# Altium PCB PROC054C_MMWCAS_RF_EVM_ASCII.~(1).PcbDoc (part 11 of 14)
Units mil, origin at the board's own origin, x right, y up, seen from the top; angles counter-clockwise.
Board outline 6299.21 x 5370.07 mil, 8 copper layers (L1 TOP, L2 GND, L3 SIGNAL 1, L4 GND, L5 SIGNAL 2, L6 SIGNAL 3, L7 GND, L8 BOTTOM), stack 53.5 mil thick; 775 components, 552 nets, 2648 pads, 7845 vias.
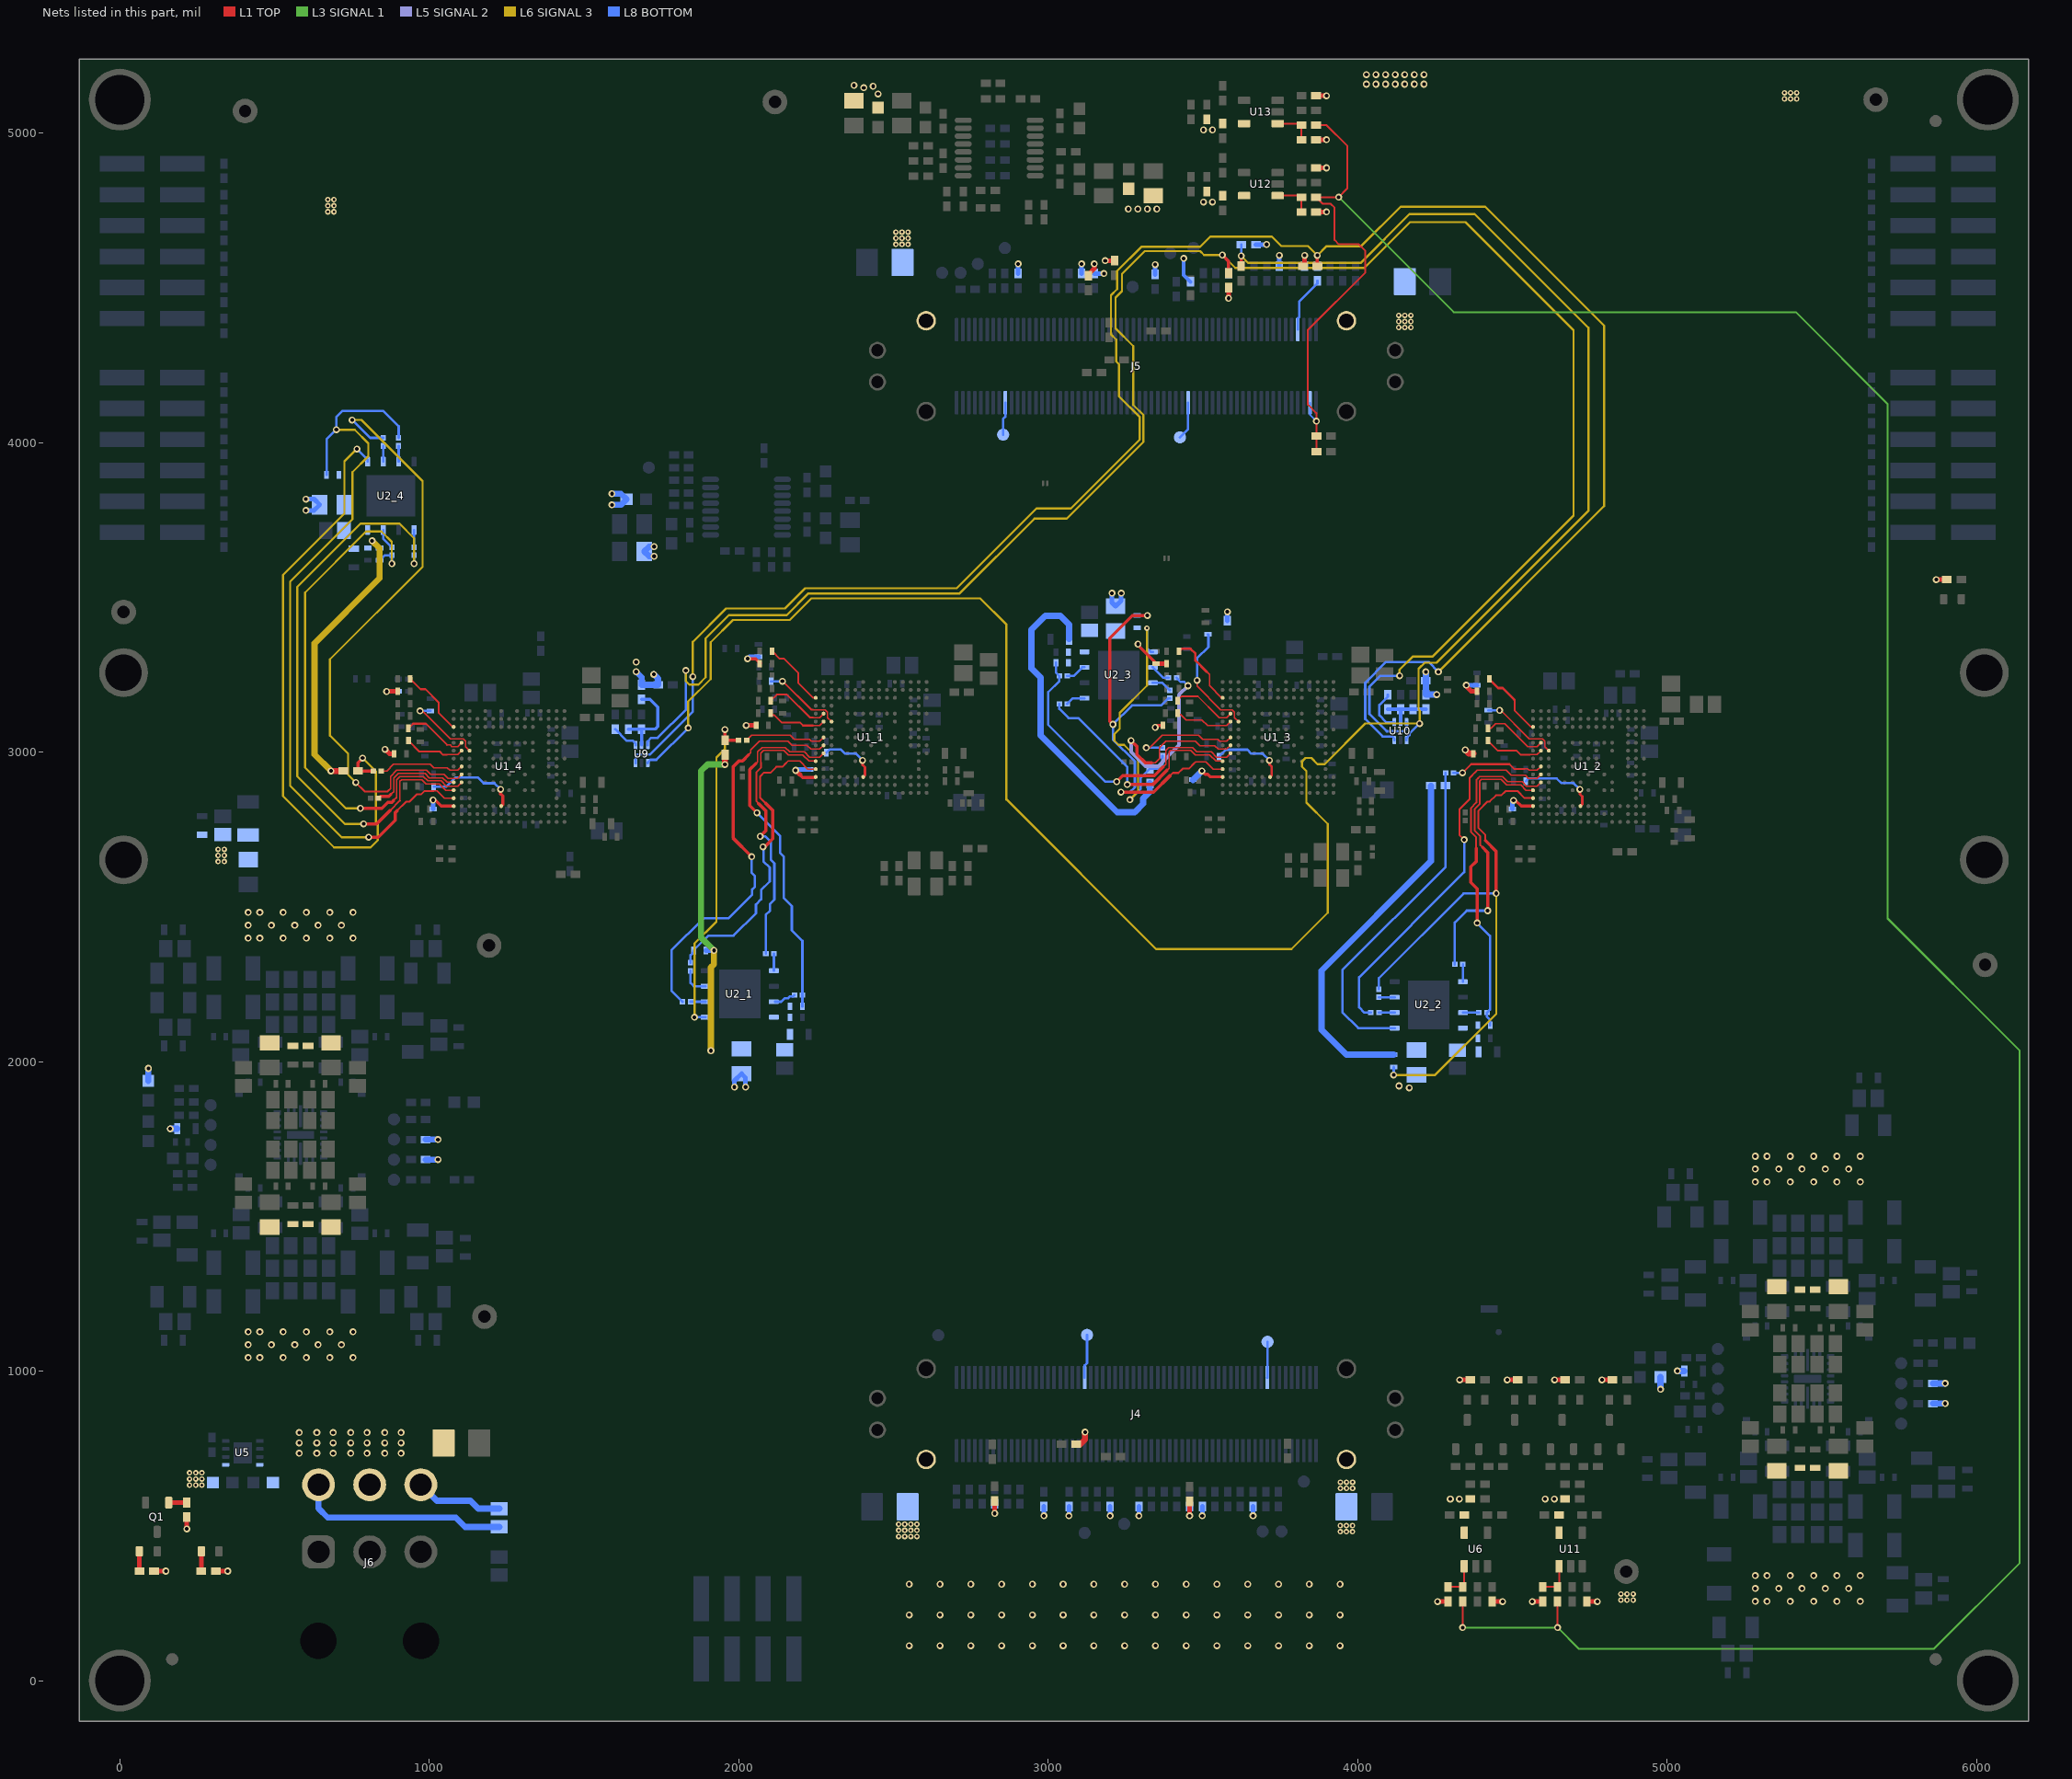
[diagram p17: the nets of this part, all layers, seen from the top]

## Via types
v1: diameter 13.77/15.74 (per signal layer), hole 5.9, L1 TOP to L2 GND, tented both sides, 5522 vias
v2: diameter 22.4, hole 12.2, L1 TOP to L8 BOTTOM, tented both sides, 1522 vias
v3: diameter 18, hole 8, L1 TOP to L8 BOTTOM, tented both sides, 727 vias
v4: diameter 18, hole 7.87, L1 TOP to L8 BOTTOM, tented top, 50 vias
v5: diameter 24, hole 12, L1 TOP to L8 BOTTOM, tented both sides, 13 vias
v6: diameter 19.68, hole 7.87, L1 TOP to L8 BOTTOM, tented top, 10 vias
v7: diameter 13.77/15.74 (per signal layer), hole 5.9, L1 TOP to L2 GND, tented top, 1 vias

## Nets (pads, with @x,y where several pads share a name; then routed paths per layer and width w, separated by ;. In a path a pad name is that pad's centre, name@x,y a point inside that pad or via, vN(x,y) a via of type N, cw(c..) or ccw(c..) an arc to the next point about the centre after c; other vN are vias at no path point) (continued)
QSPI_CLK_RS_4: R7_4.1 U1_4.R10 | length 312.9
  L1 TOP w4: 880,2867.56 885,2872.56 885,2916 900,2931 986,2931 1000,2917 1043,2917 1057.68,2902.32 U1_4.R10@1078.76,2902.31
  L1 TOP w6: 875.22,2862.78 880,2867.56
  L1 TOP w10.5: R7_4.1@836.23,2851.34 841.88,2857 869.44,2857 875.22,2862.78
QSPI_CS_1: R3_1.1 R6_1.2 U2_1.1 | length 1084.4
  L1 TOP w10.5: v2(1955.47,3072.76) R3_1.1@1955.47,3038.66 R6_1.2@1999.52,3038.66
  L6 SIGNAL 3 w6.9: v2(1856.94,2143.45) 1856.94,2381.49 1927.82,2452.37 1927.82,2982.73 1955.47,3010.37 v2(1955.47,3072.76)
  L8 BOTTOM w7.75: v2(1856.94,2143.45) U2_1.1@1893.07,2143.45
QSPI_CS_2: R3_2.1 R6_2.2 U2_2.1 | length 1101.7
  L8 BOTTOM w7.75: U2_2.1@4119.72,2108.17 4002.27,2108.17 3950.66,2159.79 3950.66,2295.48 4284.5,2629.32 R3_2.1@4284.5,2891.34 R6_2.2@4284.5,2932.79
QSPI_CS_3: R3_3.1 R6_3.2 U2_3.1 | length 942.7
  L6 SIGNAL 3 w6.9: v2(3263.95,2846.06) 3290.69,2872.8 3290.69,2978.19 3245.33,3023.55 3227.38,3023.55 3213.98,3036.95 3213.98,3058.37 3230.89,3075.29 3230.89,3126.62 3319.33,3215.06 v3(3319.33,3400.73)
  L8 BOTTOM w7.75: v2(3263.95,2846.06) 3299.18,2881.29 3299.18,2916.68 R3_3.1@3328.84,2946.33 3357.8,2946.33 3369.29,2957.81 R6_3.2@3369.29,2988.02 ; v3(3319.33,3400.73) 3319.33,3336.15 3331.48,3324 U2_3.1@3338.2,3324
QSPI_CS_4: R3_4.1 R6_4.2 U2_4.1 | length 2043.6
  L1 TOP w10.5: v2(784.43,2980.78) 769.58,2965.93 R3_4.1@769.58,2938.96 R6_4.2@818.79,2938.96
  L6 SIGNAL 3 w6.9: v2(765.87,3979.55) 725.55,3939.23 725.55,3770.66 527.16,3572.27 527.16,2857.64 692.53,2692.26 810.51,2692.26 833.15,2714.9 833.15,2765.55 827.8,2770.91 827.8,2937.42 v2(784.43,2980.78)
  L8 BOTTOM w7.75: v2(765.87,3979.55) 800.89,3944.53 U2_4.1@800.89,3938.33
QSPI_CS_RS_1: R6_1.1 U1_1.P8 | length 269.1
  L1 TOP w4: R6_1.1@2025.51,3038.66 2041.85,3055 2166.75,3055 2180,3041.75 2228.1,3041.75 2234.85,3035 2261.85,3035 U1_1.P8@2274.35,3047.5
QSPI_CS_RS_2: R6_2.1 U1_2.P8 | length 308
  L1 TOP w4: 4540.65,2946 4549,2946 4554,2941 4579.85,2941 U1_2.P8@4592.35,2953.5
  L1 TOP w6: v2(4339,2933) 4367,2961 4491,2961 4506,2946 4540.65,2946
  L8 BOTTOM w7.75: R6_2.1@4309.42,2933 v2(4339,2933)
QSPI_CS_RS_3: R6_3.1 U1_3.P8 | length 355.1
  L1 TOP w4: v2(3317,3014) 3327.98,3014 3368.98,3055 3486,3055 3500,3041 3548,3041 3554,3035 3576.85,3035 U1_3.P8@3589.35,3047.5
  L8 BOTTOM w7.75: v2(3317,3014) R6_3.1@3369.29,3014
QSPI_CS_RS_4: R6_4.1 U1_4.P8 | length 282.2
  L1 TOP w4: R6_4.1@844.78,2938.96 862.49,2938.96 884.54,2961 1003,2961 1015,2949 1058,2949 1066,2941 1091.85,2941 U1_4.P8@1104.35,2953.5
QSPI_D0_1: R30_1.1 U1_1.R11 | length 907.9
  L1 TOP w4: 2071.51,2965.93 2071.51,2996.51 2080,3005 2146,3005 2160,2991 2207,2991 2227.27,2970.73 U1_1.R11@2248.76,2970.72
  L1 TOP w6: 2064.5,2833.5 2056.46,2841.54 2056.46,2934.62 2071.51,2949.67 2071.51,2965.93
  L1 TOP w10.5: 2064.5,2833.5 2087.05,2810.95 2087.05,2745.55 v2@2069.4,2727.9
  L8 BOTTOM w7.75: v2@2069.4,2727.9 2084.8,2727.9 2104.25,2708.45 2104.25,2651.51 2115.19,2640.57 2115.19,2523.48 2100.57,2508.86 2100.57,2486.64 2087.55,2473.63 R30_1.1@2087.55,2349.27
  other v2: 2069.4,2727.78
QSPI_D0_2: R30_2.1 U1_2.R11 | length 888.5
  L1 TOP w4: 4394.22,2905.78 4400.02,2911.57 4463.43,2911.57 4481,2894 4527,2894 4544.27,2876.73 U1_2.R11@4566.76,2876.73
  L1 TOP w6: 4394.22,2905.78 4394.22,2832.02 4378,2815.79 4378,2747 4396.72,2728.28 4396.72,2699.28 4404,2692
  L1 TOP w10.5: 4404,2692 4420,2676 v2(4420,2487.75)
  L8 BOTTOM w7.75: R30_2.1@4314.21,2313.99 4314.21,2449.21 4352.75,2487.75 v2(4420,2487.75)
QSPI_D0_3: R30_3.1 U1_3.R11 | length 769.6
  L1 TOP w4: 3383.9,2940.91 3390.9,2947.91 3390.9,3000.9 3395,3005 3461,3005 3475,2991 3522,2991 3542.27,2970.73 U1_3.R11@3563.76,2970.72
  L1 TOP w10.5: v2(3255.64,2895.06) 3338.05,2895.06 3383.9,2940.91
  L8 BOTTOM w7.75: R30_3.1@3035.84,3156 3035.84,3139.82 3065.47,3110.18 3097.36,3110.18 3255.64,2951.9 v2(3255.64,2895.06)
QSPI_D0_4: R30_4.1 U1_4.R11 | length 1881.4
  L1 TOP w4: 905,2843.15 905,2906 910,2911 976,2911 990,2897 1033,2897 1053.27,2876.73 U1_4.R11@1078.76,2876.72
  L1 TOP w6: 873.33,2811.48 905,2843.15
  L1 TOP w10.5: v2(788,2768) 829.85,2768 873.33,2811.48
  L6 SIGNAL 3 w6.9: v2(788,2768) 726.98,2768 573.41,2921.58 573.41,3533.58 777.75,3737.93 903.6,3737.93 950.89,3690.64 v2(950.89,3609.06)
  L8 BOTTOM w7.75: v2(950.89,3609.06) R30_4.1@950.89,3635.98
QSPI_D0_RS_1: R30_1.2 U2_1.5 | length 55.8
  L8 BOTTOM w7.75: U2_1.5@2113.54,2293.45 R30_1.2@2113.54,2349.27
QSPI_D0_RS_2: R30_2.2 U2_2.5 | length 55.8
  L8 BOTTOM w7.75: U2_2.5@4340.2,2258.17 R30_2.2@4340.2,2313.99
QSPI_D0_RS_3: R30_3.2 U2_3.5 | length 63.4
  L8 BOTTOM w7.75: R30_3.2@3061.82,3156 3079.82,3174 U2_3.5@3117.72,3174
QSPI_D0_RS_4: R30_4.2 U2_4.5 | length 55.9
  L8 BOTTOM w7.75: R30_4.2@950.89,3661.96 U2_4.5@950.89,3717.86
QSPI_D1_1: R31_1.1 U1_1.P9 | length 1310.7
  L1 TOP w4: 2031.08,2990.33 2038.41,2997.67 2038.41,3007.02 2066.41,3035.01 2158.44,3035.01 2171.7,3021.75 2220.25,3021.75 2232.59,3009.41 2261.85,3009.41 U1_1.P9@2274.35,3021.91
  L1 TOP w10.5: 2031.08,2990.33 2012.46,2971.71 2000.63,2971.71 1981.44,2952.51 1981.44,2722.56 v2@2042,2662
  L8 BOTTOM w7.75: R31_1.1@1818.27,2193.45 1782.88,2228.84 1782.88,2360.24 1885.77,2463.13 1967.11,2463.13 2043.52,2539.54 2043.52,2556.03 2052.39,2564.9 2052.39,2599.49 2042,2609.89 v2@2042,2662
  other v2: 2042,2661.88
QSPI_D1_2: R31_2.1 U1_2.P9 | length 1203.9
  L1 TOP w4: 4380.69,2935.34 4386.35,2941 4480,2941 4496,2925 4542,2925 4551.59,2915.41 4579.85,2915.41 U1_2.P9@4592.35,2927.91
  L1 TOP w6: v2(4344.52,2716.87) 4328.62,2732.77 4328.62,2814.56 4362.05,2847.99 4362.05,2916.7 4380.69,2935.34
  L8 BOTTOM w7.75: R31_2.1@4042.84,2158.17 4021.86,2158.17 4004.78,2175.25 4004.78,2272.33 4344.52,2612.07 v2(4344.52,2716.87)
QSPI_D1_3: R31_3.1 U1_3.P9 | length 921.7
  L1 TOP w4: 3334.56,2965 3345.76,2965 3360,2979.24 3360,3014.15 3380.85,3035 3476,3035 3490,3021 3538,3021 3549.59,3009.41 3576.85,3009.41 U1_3.P9@3589.35,3021.91
  L1 TOP w10.5: v2(3268,3037) 3286.57,3018.43 3286.57,2992.7 3314.27,2965 3334.56,2965
  L5 SIGNAL 2 w12: v2(3268,3037) 3268,3000.23 3313.86,2954.37 3355.2,2954.37 3422.88,3022.05 3422.88,3185.44 v2(3451.8,3214.36)
  L8 BOTTOM w7.75: R31_3.1@3415.08,3239.82 3427.88,3227.02 3439.14,3227.02 v2(3451.8,3214.36)
QSPI_D1_4: R31_4.1 U1_4.P9 | length 1986
  L1 TOP w4: 869.32,2877.04 875,2882.72 875,2921 895,2941 991,2941 1004,2928 1048,2928 1060.59,2915.41 1091.85,2915.41 U1_4.P9@1104.35,2927.91
  L1 TOP w6: v2(762.51,2901.82) 791.72,2872.61 864.89,2872.61 869.32,2877.04
  L6 SIGNAL 3 w6.9: v2(750.85,4073.17) 780.78,4073.17 978.24,3875.71 978.24,3598.76 679.14,3299.66 679.14,3053.48 737.32,2995.31 737.32,2927 v2(762.51,2901.82)
  L8 BOTTOM w7.75: v2(750.85,4073.17) 808.81,4015.21 R31_4.1@850.89,4015.21
QSPI_D1_RS_1: R31_1.2 U2_1.2 | length 48.8
  L8 BOTTOM w7.75: R31_1.2@1844.26,2193.45 U2_1.2@1893.07,2193.45
QSPI_D1_RS_2: R31_2.2 U2_2.2 | length 50.9
  L8 BOTTOM w7.75: R31_2.2@4068.82,2158.17 U2_2.2@4119.72,2158.17
QSPI_D1_RS_3: R31_3.2 U2_3.2 | length 65.1
  L8 BOTTOM w7.75: U2_3.2@3338.2,3274 3372.38,3239.82 R31_3.2@3389.1,3239.82
QSPI_D1_RS_4: R31_4.2 U2_4.2 | length 50.9
  L8 BOTTOM w7.75: U2_4.2@850.89,3938.33 R31_4.2@850.89,3989.23
QSPI_D2_1: R27_1.2 R32_1.1 U1_1.R12 | length 1009.3
  L1 TOP w4: 2189.08,2971 2197,2971 2222.86,2945.14 U1_1.R12@2248.76,2945.13
  L1 TOP w4.9: 2153.81,2965.29 2159.52,2971 2189.08,2971
  L1 TOP w6: 2088,2834 2069,2853 2069,2921.42 2081.58,2934 2103.44,2934 2121.77,2952.32 2140.84,2952.32 2153.81,2965.29
  L1 TOP w10.5: v2@2078.5,2694.1 2084.43,2694.1 2110.35,2720.02 2110.35,2811.65 2088,2834
  L8 BOTTOM w7.75: R32_1.1@1844.26,2319.43 1844.26,2343.58 1854.26,2353.58 R27_1.2@1854.26,2359.18 1902.03,2406.95 1983.18,2406.95 2055.67,2479.44 2055.67,2507.44 2072.49,2524.26 2072.49,2554.39 2100.18,2582.09 2100.18,2626.82 2080,2647 2080,2692.6 v2@2078.5,2694.1
  other v2: 2078.5,2693.98
QSPI_D2_2: R27_2.2 R32_2.1 U1_2.R12 | length 1859.4
  L1 TOP w6: 4413.01,2713.99 4413.01,2731.99 4390.35,2754.65 4390.35,2810.73 4419.98,2840.35 4427.2,2840.35 4446.85,2860 4464.17,2860 4478.17,2874 4517,2874 4539.87,2851.13 U1_2.R12@4566.76,2851.13
  L1 TOP w10.5: 4413.01,2713.99 4448,2679 v2(4448,2543.39)
  L6 SIGNAL 3 w6.9: v2(4116.64,1956.94) 4250.75,1956.94 4448,2154.2 v2(4448,2543.39)
  L8 BOTTOM w7.75: R32_2.1@4068.82,2234.15 4068.82,2270 4342.21,2543.39 v2(4448,2543.39) ; v2(4116.64,1956.94) R27_2.2@4116.64,1982.51
QSPI_D2_3: R27_3.2 R32_3.1 U1_3.R12 | length 1344.2
  L1 TOP w4: 3471.82,2963.62 3477.2,2969 3510,2969 3533.86,2945.14 U1_3.R12@3563.76,2945.13
  L1 TOP w6: 3394.44,2924.44 3402.79,2932.79 3420.79,2932.79 3434.67,2946.67 3454.87,2946.67 3471.82,2963.62
  L1 TOP w10.5: v2(3209,3089.6) 3198.84,3099.75 3198.84,3368.15 3271.94,3441.24 v2(3320.35,3441.24) ; v2(3235.29,2870.65) 3340.65,2870.65 3394.44,2924.44
  L8 BOTTOM w7.75: v2(3235.29,2870.65) 3264.43,2870.65 3280.08,2886.3 3280.08,2969.98 3209,3041.06 v2(3209,3089.6) 3270.53,3151.13 3365.27,3151.13 3388.02,3173.88 R32_3.1@3393.01,3173.88 ; R27_3.2@3292.73,3441.24 v2(3320.35,3441.24)
QSPI_D2_4: R27_4.2 R32_4.1 U1_4.R12 | length 2483.7
  L1 TOP w4: 1014.53,2874.24 1025.76,2874.24 1048.86,2851.14 U1_4.R12@1078.76,2851.13
  L1 TOP w6: 896.36,2811.17 925,2839.81 935.7,2839.81 958.92,2863.04 973.3,2863.04 984.5,2874.24 1014.53,2874.24
  L1 TOP w10.5: v2(804,2725) 835.1,2725 889.39,2779.29 889.39,2804.2 896.36,2811.17
  L6 SIGNAL 3 w6.9: v2(699.62,4041.66) 758.97,4041.66 803.02,3997.61 803.02,3955.88 751.72,3904.58 751.72,3752.25 550.28,3550.81 550.28,2891.36 716.65,2725 v2(804,2725)
  L8 BOTTOM w7.75: R27_4.2@668.22,3895.75 668.22,4010.26 v2(699.62,4041.66) 699.62,4082.81 719.53,4102.72 850.89,4102.72 900.89,4052.72 R32_4.1@900.89,4015.21
QSPI_D2_RS_1: R32_1.2 U2_1.3 | length 92.4
  L8 BOTTOM w7.75: R32_1.2@1844.26,2293.44 1844.26,2254.36 1855.17,2243.45 U2_1.3@1893.07,2243.45
QSPI_D2_RS_2: R32_2.2 U2_2.3 | length 50.9
  L8 BOTTOM w7.75: R32_2.2@4068.82,2208.17 U2_2.3@4119.72,2208.17
QSPI_D2_RS_3: R32_3.2 U2_3.3 | length 64.8
  L8 BOTTOM w7.75: U2_3.3@3338.2,3224 3368.87,3224 R32_3.2@3393.01,3199.87
QSPI_D2_RS_4: R32_4.2 U2_4.3 | length 50.9
  L8 BOTTOM w7.75: U2_4.3@900.89,3938.33 R32_4.2@900.89,3989.23
QSPI_D3_1: R28_1.2 R33_1.1 U1_1.P10 | length 1141
  L1 TOP w4: 2054.98,2962.98 2060.79,2968.79 2060.79,3000.79 2075.01,3015.01 2150.14,3015.01 2164.15,3001 2212,3001 2229.18,2983.82 2261.85,2983.82 U1_1.P10@2274.35,2996.31
  L1 TOP w10.5: 2054.98,2962.98 2035.81,2943.81 2035.81,2827.19 v2@2059,2804
  L8 BOTTOM w7.75: v2@2059,2804 2134,2729 2134,2673.76 2145.86,2661.9 2145.86,2528.37 2171.6,2502.63 2171.6,2424.11 2205.91,2389.81 R33_1.1@2205.91,2215.45 R28_1.2@2205.91,2178.18
  other v2: 2059,2803.88
QSPI_D3_2: R28_2.2 R33_2.1 U1_2.P10 | length 1078.6
  L1 TOP w4: 4388.98,2915.33 4393.85,2920.2 4468.95,2920.2 4485.15,2904 4532,2904 4546.18,2889.82 4579.85,2889.82 U1_2.P10@4592.35,2902.32
  L1 TOP w6: 4383,2688.83 4383,2725 4366,2742 4366,2818.96 4384.12,2837.08 4384.12,2910.47 4388.98,2915.33
  L1 TOP w10.5: 4383,2688.83 4383,2646.71 4366,2629.71 4366,2578.75 4386.34,2558.41 v2(4386.34,2447.74)
  L8 BOTTOM w7.75: v2(4386.34,2447.74) 4428.03,2406.05 4428.03,2168.13 R33_2.1@4418.08,2158.17 4418.08,2145.12 4428.64,2134.56 R28_2.2@4428.64,2117.67
QSPI_D3_3: R28_3.2 R33_3.1 U1_3.P10 | length 974.8
  L1 TOP w4: 3370.96,2952.36 3380,2961.4 3380,3005 3390,3015 3466,3015 3480,3001 3527,3001 3544.18,2983.82 3576.85,2983.82 U1_3.P10@3589.35,2996.31
  L1 TOP w10.5: v2(3221.41,2904.61) 3240.98,2924.17 3342.78,2924.17 3370.96,2952.36
  L8 BOTTOM w7.75: R28_3.2@3025.36,3289.27 3025.36,3256.48 R33_3.1@3035.84,3246 3035.84,3229.7 3000.02,3193.88 3000.02,3088.53 3183.94,2904.61 v2(3221.41,2904.61)
QSPI_D3_4: R28_4.2 R33_4.1 U1_4.P10 | length 1739
  L1 TOP w4: 892.97,2851.96 895,2853.99 895,2910.99 905,2920.99 981,2920.99 995,2906.99 1038,2906.99 1055.18,2889.81 1091.85,2889.81 U1_4.P10@1104.35,2902.31
  L1 TOP w6: 884.5,2843.49 892.97,2851.96
  L1 TOP w10.5: v2(777.5,2818.49) 846.59,2818.49 866.09,2837.99 879,2837.99 884.5,2843.49
  L6 SIGNAL 3 w6.9: v2(777.5,2818.49) 730.21,2818.49 598.6,2950.1 598.6,3515.57 795.79,3712.77 845.26,3712.77 878.89,3679.14 v2(878.89,3609.06)
  L8 BOTTOM w7.75: R28_4.2@839.38,3619.4 855.95,3635.98 R33_4.1@878.89,3635.98 v2(878.89,3609.06)
QSPI_D3_RS_1: R33_1.2 U2_1.7 | length 71.6
  L8 BOTTOM w7.75: U2_1.7@2117.47,2193.45 2137.37,2193.45 2149.08,2205.16 2159.64,2205.16 2165.33,2210.86 2175.33,2210.86 R33_1.2@2179.92,2215.45
QSPI_D3_RS_2: R33_2.2 U2_2.7 | length 51.9
  L8 BOTTOM w7.75: U2_2.7@4340.2,2158.17 R33_2.2@4392.1,2158.17
QSPI_D3_RS_3: R33_3.2 U2_3.7 | length 67.5
  L8 BOTTOM w7.75: R33_3.2@3061.82,3246 3082.81,3246 3110.81,3274 U2_3.7@3117.72,3274
QSPI_D3_RS_4: R33_4.2 U2_4.7 | length 67.5
  L8 BOTTOM w7.75: U2_4.7@850.89,3717.86 850.89,3689.96 R33_4.2@878.89,3661.96
QSPI_FLASH_3V3_1: C6_1.1 C7_1.1 C8_1.1 R3_1.2 R27_1.1 R28_1.1 R29_1.1 U2_1.8 | length 1068.6
  L1 TOP w20: v2(1955.47,2960.16) R3_1.2@1955.47,2991.41
  L3 SIGNAL 1 w20: v2(1920.09,2359.18) 1877.94,2401.33 1877.94,2938.65 1899.46,2960.16 v2(1955.47,2960.16)
  L6 SIGNAL 3 w20: v2(1910.09,2035.18) 1910.09,2304.57 1920.09,2314.57 v2(1920.09,2359.18)
  L8 BOTTOM w15: R27_1.1@1894.26,2359.18 v2(1920.09,2359.18)
QSPI_FLASH_3V3_2: C6_2.1 C7_2.1 C8_2.1 R3_2.2 R27_2.1 R28_2.1 R29_2.1 U2_2.8 | length 1201.7
  L8 BOTTOM w20: R27_2.1@4116.64,2022.51 3963.83,2022.51 3883.22,2103.12 3883.22,2293.73 4237.25,2647.76 R3_2.2@4237.25,2891.34
QSPI_FLASH_3V3_3: C6_3.1 C7_3.1 C8_3.1 R3_3.2 R27_3.1 R28_3.1 R29_3.1 U2_3.8 | length 1073.9
  L8 BOTTOM w20: C7_3.1@3067.86,3364.87 3067.86,3412.18 3039.51,3440.52 2990.81,3440.52 2946.13,3395.84 2946.13,3270.34 2975.25,3241.22 2975.25,3053.67 3222.91,2806 3279.58,2806 3306.8,2833.22 3306.8,2850.13 3328.84,2872.17 R3_3.2@3328.84,2899.09
QSPI_FLASH_3V3_4: C6_4.1 C7_4.1 C8_4.1 R3_4.2 R27_4.1 R28_4.1 R29_4.1 U2_4.8 | length 903.2
  L1 TOP w20: v2(682.32,2938.96) R3_4.2@722.34,2938.96
  L6 SIGNAL 3 w20: v2(682.32,2938.96) 629.15,2992.12 629.15,3351.52 839.49,3561.86 839.49,3658.66 v2(815.19,3682.96)
SDA_RS_1: R13_1.2 U1_1.R3 | length 221.9
  L1 TOP w6: R13_1.2@2108,3326 2132.6,3301.4 2146.9,3301.4 2192,3256.29 2192,3224.18 2240.73,3175.45 U1_1.R3@2248.76,3175.45
SDA_RS_2: R13_2.2 U1_2.R3 | length 225.8
  L1 TOP w6: 4507,3168.16 4507,3134.97 4560.52,3081.45 U1_2.R3@4566.76,3081.45
  L1 TOP w8: R13_2.2@4425.9,3237 4425.9,3235.1 4454.14,3206.86 4468.3,3206.86 4507,3168.16
SDA_RS_3: R13_3.2 U1_3.R3 | length 244.1
  L1 TOP w4: 3512.28,3259.72 3521,3251 3521,3214.56 3560.11,3175.45 U1_3.R3@3563.76,3175.45
  L1 TOP w8: R13_3.2@3422.9,3326 3430.8,3333.9 3460.21,3333.9 3475.94,3318.16 3475.94,3296.06 3512.28,3259.72
SDA_RS_4: R13_4.2 U1_4.R3 | length 225.1
  L1 TOP w4: 1053.68,3103.12 1075.35,3081.45 U1_4.R3@1078.76,3081.45
  L1 TOP w6: R13_4.2@937.9,3237 971.67,3203.23 987.47,3203.23 1029.87,3160.83 1029.87,3126.93 1053.68,3103.12
SPI_HOST_INTR1_RS_1: R10_1.1 U1_1.P6 | length 193.3
  L1 TOP w4: 2240.01,3085.86 2261.53,3085.86 U1_1.P6@2274.35,3098.68
  L1 TOP w6: R10_1.1@2103,3126 2109.12,3119.88 2114.54,3119.88 2138.62,3095.8 2197.43,3095.8 2207.37,3085.86 2240.01,3085.86
SPI_HOST_INTR1_RS_2: R10_2.1 U1_2.P6 | length 195.4
  L1 TOP w4: 4556.13,2991.86 4579.53,2991.86 U1_2.P6@4592.35,3004.68
  L1 TOP w6: R10_2.1@4420.91,3037 4452.45,3005.46 4513.1,3005.46 4526.7,2991.86 4556.13,2991.86
SPI_HOST_INTR1_RS_3: R10_3.1 U1_3.P6 | length 192.1
  L1 TOP w4: R10_3.1@3418.91,3126 3423.89,3121.02 3428.5,3121.02 3445.15,3104.37 3496.94,3104.37 3515.13,3086.18 3576.85,3086.18 U1_3.P6@3589.35,3098.68
SPI_HOST_INTR1_RS_4: R10_4.1 U1_4.P6 | length 195.5
  L1 TOP w4: 1056.91,2992.18 1091.85,2992.18 U1_4.P6@1104.35,3004.68
  L1 TOP w6: R10_4.1@933,3037 933,3036.28 967.48,3001.79 1033.74,3001.79 1043.36,2992.18 1056.91,2992.18
SPI_MISO1_RS_1: R12_1.1 U1_1.P5 | length 215.6
  L1 TOP w4: 2239.63,3111.77 2261.85,3111.77 U1_1.P5@2274.35,3124.27
  L1 TOP w6: R12_1.1@2103,3166 2123,3186 2155.62,3186 2229.85,3111.77 2239.63,3111.77
SPI_MISO1_RS_2: R12_2.1 U1_2.P5 | length 213.6
  L1 TOP w4: 4557.73,3017.77 4579.85,3017.77 U1_2.P5@4592.35,3030.27
  L1 TOP w4.9: R12_2.1@4420.89,3077 4431.03,3077 4446.03,3092 4476,3092 4550.23,3017.77 4557.73,3017.77
SPI_MISO1_RS_3: R12_3.1 U1_3.P5 | length 211
  L1 TOP w4: 3548.24,3115.92 3552.39,3111.77 3576.85,3111.77 U1_3.P5@3589.35,3124.27
  L1 TOP w4.9: R12_3.1@3418.89,3166 3418.89,3167.92 3431.24,3180.27 3483.89,3180.27 3548.24,3115.92
SPI_MISO1_RS_4: R12_4.1 U1_4.P5 | length 213.4
  L1 TOP w4: 1057.76,3023.24 1067.76,3023.24 1073.23,3017.77 1091.85,3017.77 U1_4.P5@1104.35,3030.27
  L1 TOP w6: R12_4.1@932.89,3077 947.68,3091.79 989.21,3091.79 1057.76,3023.24
SYSTEM_1V8: C18.1 C19.1 C20.1 C175.1 L34.1 R35.2
  other v2: 3259.09,4754.58 3289.73,4754.58 3320.38,4754.58 3351.02,4754.58
  other v3: 317.57,2646.28 337.26,2646.28 317.57,2665.96 337.26,2665.96 317.57,2685.65 337.26,2685.65 672.2,4745.71 691.88,4745.71 672.2,4765.4 691.88,4765.4 672.2,4785.08 691.88,4785.08
SYSTEM_3V3: C148_1.1 C148_2.1 C148_3.1 C148_4.1 C162.1 C163.1 C164.1 C165.1 C169.1 C181.1 C197.1 C198.1 C203.1 L33.1 L35.1 R29_1.2 R29_2.2 R29_3.2 R29_4.2 R37.2 R46.1 R47.2 R61.2 R70.1 R71.2 R86.2 R87.2 R88.2 R89.2 R90.2 R91.2 R92.2 R93.2 R150.2 R164.1 R166.2 R167.2 R168.2 R173.1 R174_1.2 R174_2.2 R174_3.2 R174_4.2 R175_1.2 R175_2.2 R175_3.2 R175_4.2 R176_1.2 R176_2.2 R176_3.2 R176_4.2 R177_1.2 R177_2.2 R177_3.2 R177_4.2 R178_1.2 R178_2.2 R178_3.2 R178_4.2 R179_1.2 R179_2.2 R179_3.2 R179_4.2 R180_1.2 R180_2.2 R180_3.2 R180_4.2 R181_1.2 R181_2.2 R181_3.2 R181_4.2 R193.2 R195.2 R206.2 R207.2 U1_1.R13 U1_2.R13 U1_3.R13 U1_4.R13 U5.1 U6.5 U11.5 U12.5 U13.5 | length 3056.5
  L1 TOP w10: v2(1012,2845) 1019,2845 1038.45,2825.55 U1_4.R13@1078.76,2825.55 ; v2(2028.5,3301.5) 2054.7,3301.5 R180_1.2@2070.2,3286 ; 2198,2927 2207,2918 2247.21,2918 U1_1.R13@2248.76,2919.55 ; v2(3290,3349) 3290,3345.61 3349.08,3286.53 R181_3.2@3349.08,3286 ; v2(3346,3080) 3352,3086 R177_3.2@3373.6,3086 ; v2(3497,2939) 3507.39,2928.61 3515.55,2928.61 3524.16,2920 3563.31,2920 U1_3.R13@3563.76,2919.55 ; v2(4504,2844) 4510,2844 4528.45,2825.55 U1_2.R13@4566.76,2825.55
  L1 TOP w15: v2(216.13,489.93) R195.2@216.13,527.89 ; v2(857,3009) 871,2995 R177_4.2@886.4,2995 ; v2@862,3197 R180_4.2@897.91,3197 ; v2(2024,3086) R177_1.2@2056.4,3086 ; v2(2184,2941) 2198,2927 ; v2(2827.21,540.28) R176_1.2@2827.21,580.9 ; R175_4.2@3130.51,4539.69 3130.51,4543.91 3149,4562.41 v2(3149,4577.44) ; v2(3184.17,4587.61) R176_4.2@3215.4,4587.61 ; R181_3.2@3349.08,3286 R180_3.2@3382.91,3286 ; v2(3457,532.56) R175_2.2@3457,579.22 ; v2(3583,4466.2) R168.2@3583,4500 ; R166.2@3822.75,4570.25 3829,4576.49 v2(3829,4604.76) ; R91.2@3865.5,4745.42 v2(3899.65,4745.42) ; R90.2@3865.5,4887.63 v2(3899.65,4887.63) ; R93.2@3865.5,4978.47 v2(3899.65,4978.47) ; R92.2@3865.5,5120.67 v2(3899.65,5120.67) ; v2(4258.03,255.59) R87.2@4292.19,255.59 ; v2(4351.29,3216.41) 4351.29,3212 4366.29,3197 R180_2.2@4385.91,3197 ; R86.2@4434.39,255.59 v2(4468.55,255.59) ; v2(4564.48,255.59) R89.2@4598.64,255.59 ; R88.2@4740.84,255.59 v2(4775,255.59) ; v2(5869.75,3557.54) R193.2@5903.9,3557.54
  L1 TOP w20: R178_1.2@3090.34,764 3103.52,764 3119.1,779.58 v2(3119.1,802.9) ; v2(4348,3007) 4360,2995 R177_2.2@4374.4,2995
  L8 BOTTOM w10: v2(862,3195.9) R181_4.2@899.06,3195.9
  L8 BOTTOM w12: v2(3437.73,4595.35) 3437.73,4541.94 R178_3.2@3460,4519.67
  L8 BOTTOM w15: v2(601.18,3781.05) 627.69,3781.05 R29_4.2@645.87,3799.23 627.69,3817.41 v2(601.18,3817.41) ; C148_4.1@1012,2815.58 v2(1012,2845) ; v2(1985.88,1917.9) 1985.88,1937.82 R29_1.2@2009.01,1960.95 2022.13,1947.82 v2(2022.13,1917.9) ; v2(2028.5,3301.5) 2035.23,3308.23 R181_1.2@2063.84,3308.23 ; v2(2184,2941) 2187.28,2944.28 C148_1.1@2229,2944.28 ; v2(2827.21,540.28) R175_1.2@2827.21,570.9 ; R174_4.2@2903,4546.21 v2(2903,4577.44) ; v2(2986,532.56) R150.2@2986,563.18 ; v2(3067,532.56) R179_1.2@3067,563.18 ; R178_4.2@3108,4546.21 v2(3108,4577.44) ; R179_4.2@3149,4546.21 v2(3180.23,4546.21) ; v2(3200,532.56) R174_1.2@3200,563.18 ; v2(3206.11,3513.53) 3206.11,3483.19 R29_3.2@3218.01,3471.29 3236.19,3489.47 v2(3236.19,3513.53) ; v2(3293,532.56) R176_2.2@3293,563.18 ; R174_3.2@3346,4543.24 v2(3346,4575.08) ; v2(3457,532.56) R179_2.2@3457,563.18 ; v2(3498,532.56) R178_2.2@3498,563.18 ; R179_3.2@3578.91,3424.58 v2(3578.91,3453.53) ; v2(3662,532.56) R174_2.2@3662,563.18 ; R167.2@3671.24,4640.08 v2(3705.76,4640.08) ; R175_3.2@3747,4570.25 v2(3747,4604.76) ; R176_3.2@3829,4570.25 v2(3829,4604.76) ; v2(4351.29,3216.41) R181_2.2@4386.19,3216.41 ; C148_2.1@4500,2815.58 4500,2840 v2(4504,2844)
  L8 BOTTOM w20: R46.1@988.28,1683.21 v2(1028.15,1683.21) ; R47.2@988.28,1748.23 v2(1028.15,1748.23) ; v2(1590.21,3798.87) 1619.54,3798.87 L35.1@1637.54,3816.87 1619.54,3834.87 v2(1590.21,3834.87) ; v2(1668.58,3259.7) 1686.31,3241.98 R164.1@1686.31,3217.45 C197.1@1739.32,3217.44 1739.32,3237.56 v2(1725.47,3251.41) ; v2(1726.42,3632.62) 1710.6,3632.62 C181.1@1695.02,3648.2 1710.6,3663.78 v2(1726.42,3663.78) ; C148_3.1@3467.98,2909.98 v2(3497,2939) ; v2(4220.47,3259.25) C198.1@4220.47,3230.71 R173.1@4220.47,3185.83 v2(4255.81,3185.83) ; R70.1@5859,895.36 v2(5898.87,895.36) ; R71.2@5859,960.38 v2(5898.87,960.38)
  other v2: 4299.6,586.56 4329.13,586.56 4606.05,586.56 4635.58,586.56 4166.81,1915.43 4133.82,1921.54 1668.45,3290.77 3501.68,4777.32 3531.22,4777.32 3501.68,5010.37 3531.22,5010.37 2450.31,5126.39 2404.21,5146.62 2434.12,5151.52 2372.39,5154.46
  other v3: 4851.06,260.16 4870.74,260.16 4890.43,260.16 4851.06,279.85 4870.74,279.85 4890.43,279.85 225.44,631.86 245.12,631.86 264.81,631.86 225.44,651.54 245.12,651.54 264.81,651.54 225.44,671.23 245.12,671.23 264.81,671.23 5379.55,5110.56 5399.23,5110.56 5418.92,5110.56 5379.55,5130.25 5399.23,5130.25 5418.92,5130.25
SYSTEM_3V3_LED: Q1.1 R195.1 | length 58.3
  L1 TOP w15: Q1.1@157.85,575.13 R195.1@216.13,575.13
SYSTEM_3V3_LED_PW: DS3.1 R194.1 | length 63.8
  L1 TOP w15: R194.1@63.36,353.83 DS3.1@63.36,417.61
SYSTEM_5V0: C39.1 C44.1 C51.1 C56.1 C97.1 C102.1 C109.1 C114.1 C190.1 C191.1 C192.1 C193.1 C194.1 C202.1 J4.P3 J4.P4 J5.P1 J5.P2 J6.5 J6.6 L9.1 L10.1 L11.1 L12.1 L25.1 L26.1 L27.1 L28.1 R19.1 R34.2 R44.1 R59.2 R68.1 R192.2 R194.2 R196.2 R197.2 R200.2 R201.2 U5.8 | length 623.1
  L1 TOP w15: R194.2@110.6,353.83 v2(148.56,353.83) ; R192.2@310.6,353.83 v2(348.56,353.83) ; v2(4330.07,971.8) R196.2@4364.23,971.8 ; v2(4483.3,971.8) R201.2@4517.45,971.8 ; v2(4636.52,971.8) R197.2@4670.68,971.8 ; v2(4789.75,971.8) R200.2@4823.9,971.8
  L8 BOTTOM w20: R34.2@92.28,1938.09 v2(92.28,1977.96) ; v2(162.55,1783.21) R44.1@185.28,1783.21 ; J6.6@972.72,632.78 1024.38,581.12 1132.73,581.12 1158.2,555.65 R19.1@1226.16,555.65 ; v2(4978.78,941.32) R59.2@4978.78,981.19 ; v2(5033.27,1000.35) R68.1@5056.01,1000.35
  other v2: 2551.09,112.68 2650.53,112.68 2749.97,112.68 2849.41,112.68 2948.85,112.68 3048.29,112.68 3147.73,112.68 3247.17,112.68 3346.61,112.68 3446.05,112.68 3545.49,112.68 3644.94,112.68 3744.38,112.68 3843.82,112.68 3943.26,112.68 2551.09,212.12 2650.53,212.12 2749.97,212.12 2849.41,212.12 2948.85,212.12 3048.29,212.12 3147.73,212.12 3247.17,212.12 3346.61,212.12 3446.05,212.12 3545.49,212.12 3644.94,212.12 3744.38,212.12 3843.82,212.12 3943.26,212.12 5285.29,256.03 5322.96,256.03 5398.29,256.03 5473.63,256.03 5548.96,256.03 5624.29,256.03 5285.29,297.53 5360.63,297.53 5435.96,297.53 5511.29,297.53 5586.63,297.53 2551.09,311.56 2650.53,311.56 2749.97,311.56 2849.41,311.56 2948.85,311.56 3048.29,311.56 3147.73,311.56 3247.17,311.56 3346.61,311.56 3446.05,311.56 3545.49,311.56 3644.94,311.56 3744.38,311.56 3843.82,311.56 3943.26,311.56 5285.29,339.03 5322.96,339.03 5398.29,339.03 5473.63,339.03 5548.96,339.03 5624.29,339.03 579.51,734.71 636.51,734.71 689.21,734.71 746.21,734.71 798.91,734.71 855.91,734.71 908.61,734.71 579.51,768.04 636.51,768.04 689.21,768.04 746.21,768.04 798.91,768.04 855.91,768.04 908.61,768.04 579.51,801.37 636.51,801.37 689.21,801.37 746.21,801.37 798.91,801.37 855.91,801.37 908.61,801.37 414.57,1043.88 452.24,1043.88 527.57,1043.88 602.9,1043.88 678.24,1043.88 753.57,1043.88 414.57,1085.38 489.9,1085.38 565.24,1085.38 640.57,1085.38 715.9,1085.38 414.57,1126.88 452.24,1126.88 527.57,1126.88 602.9,1126.88 678.24,1126.88 753.57,1126.88 5285.29,1611.18 5322.96,1611.18 5398.29,1611.18 5473.63,1611.18 5548.96,1611.18 5624.29,1611.18 5285.29,1652.68 5360.63,1652.68 5435.96,1652.68 5511.29,1652.68 5586.63,1652.68 5285.29,1694.18 5322.96,1694.18 5398.29,1694.18 5473.63,1694.18 5548.96,1694.18 5624.29,1694.18 414.57,2399.04 452.24,2399.04 527.57,2399.04 602.9,2399.04 678.24,2399.04 753.57,2399.04 414.57,2440.54 489.9,2440.54 565.24,2440.54 640.57,2440.54 715.9,2440.54 414.57,2482.04 452.24,2482.04 527.57,2482.04 602.9,2482.04 678.24,2482.04 753.57,2482.04 4028.33,5158.13 4059.33,5158.13 4090.33,5158.13 4121.33,5158.13 4152.33,5158.13 4183.33,5158.13 4214.33,5158.13 4028.33,5189.13 4059.33,5189.13 4090.33,5189.13 4121.33,5189.13 4152.33,5189.13 4183.33,5189.13 4214.33,5189.13
  other v3: 2516.73,465.73 2536.41,465.73 2556.1,465.73 2575.78,465.73 3944.01,480.96 3963.69,480.96 3983.38,480.96 2516.73,485.42 2536.41,485.42 2556.1,485.42 2575.78,485.42 3944.01,500.65 3963.69,500.65 3983.38,500.65 2516.73,505.1 2536.41,505.1 2556.1,505.1 2575.78,505.1 3944.46,621.51 3964.14,621.51 3983.83,621.51 3944.46,641.2 3964.14,641.2 3983.83,641.2 4132.74,4371.76 4152.43,4371.76 4172.11,4371.76 4132.74,4391.45 4152.43,4391.45 4172.11,4391.45 4132.74,4411.13 4152.43,4411.13 4172.11,4411.13 2507.71,4640.63 2527.39,4640.63 2547.08,4640.63 2507.71,4660.32 2527.39,4660.32 2547.08,4660.32 2507.71,4680 2527.39,4680 2547.08,4680
SYSTEM_5V0_LED: DS1.1 R192.1 | length 63.8
  L1 TOP w15: R192.1@263.36,353.83 DS1.1@263.36,417.61
SYSTEM_5V0_SENSE: J6.4 R19.2 | length 685.3
  L8 BOTTOM w20: J6.4@642.01,632.78 642.01,556.46 671.54,526.93 1085.35,526.93 1115.69,496.59 R19.2@1226.16,496.59
SYSTEM_PGOOD: J5.119 R38.1 R62.1 R189.1 R204.1 R205.1 R212.1 | length 9560.7
  L1 TOP w6: R62.1@3865.5,5025.87 3899.65,5025.87 3966.41,4959.12 3966.41,4820.66 v2(3938.57,4792.82) R38.1@3865.5,4792.82 3886.67,4771.65 3912.34,4771.65 3925.32,4758.67 3925.32,4654.89 3939.38,4640.83 4003.94,4640.83 4024.92,4619.85 4024.92,4549.91 3839.48,4364.47 3839.48,4122.49 3867,4094.97 v2(3867,4069) R204.1@3867,4020.74 R205.1@3867,3971.03 ; v2(4339.59,171.43) R189.1@4339.59,255.59 ; v2(4646.04,171.43) R212.1@4646.04,255.59
  L3 SIGNAL 1 w6: v2(3938.57,4792.82) 4310.11,4421.29 5416.14,4421.29 5712.68,4124.75 5712.68,2462.43 6139.39,2035.73 6139.39,380.1 5861.89,102.6 4714.87,102.6 v2(4646.04,171.43) v2(4339.59,171.43)
  L8 BOTTOM w6: J5.119@3845.94,4128.84 3845.94,4090.06 v2(3867,4069)
SYSTEM_PGOOD1_GS: R87.1 R189.2 U6.1 | length 116.2
  L1 TOP w6: R87.1@4292.19,302.83 R189.2@4339.59,302.83 4344.59,307.83 U6.1@4344.59,369.58
SYSTEM_PGOOD2_GS: R89.1 R212.2 U11.1 | length 116.2
  L1 TOP w6: R89.1@4598.64,302.83 R212.2@4646.04,302.83 4651.04,307.83 U11.1@4651.04,369.58
SYSTEM_PGOOD3_GS: R38.2 R91.1 U12.1 | length 126.2
  L1 TOP w6: U12.1@3741.51,4797.82 3813.25,4797.82 R38.2@3818.25,4792.82 R91.1@3818.25,4745.42
SYSTEM_PGOOD4_GS: R62.2 R93.1 U13.1 | length 126.2
  L1 TOP w6: U13.1@3741.51,5030.87 3813.25,5030.87 R62.2@3818.25,5025.87 R93.1@3818.25,4978.47
TDO_RS_1: R8_1.1 U1_1.J13 | length 195.3
  L1 TOP w8: v2(2400.34,2973.54) 2400.34,2958.25 2407.9,2950.69 2407.9,2925.15 U1_1.J13@2402.3,2919.55
  L8 BOTTOM w7.75: R8_1.1@2283.7,2998.15 2294.54,3009 2329.72,3009 2343.1,2995.62 2378.26,2995.62 v2(2400.34,2973.54)
TDO_RS_2: R8_2.1 U1_2.J13 | length 252.2
  L1 TOP w8: v2(4718.34,2879.54) 4718.34,2864.33 4725.85,2856.82 4725.85,2831.1 U1_2.J13@4720.3,2825.55
  L8 BOTTOM w7.75: R8_2.1@4543.9,2906 4552.85,2914.95 4643.17,2914.95 4658.52,2899.6 4698.28,2899.6 v2(4718.34,2879.54)
TDO_RS_3: R8_3.1 U1_3.J13 | length 246.5
  L1 TOP w8: v2(3715.34,2973.54) 3715.34,2959.61 3722.42,2952.52 3722.42,2924.67 U1_3.J13@3717.3,2919.55
  L8 BOTTOM w7.75: R8_3.1@3551.46,2985.2 3574.07,3007.81 3643.97,3007.81 3656.78,2995 3693.88,2995 v2(3715.34,2973.54)
TDO_RS_4: R8_4.1 U1_4.J13 | length 303.5
  L1 TOP w10.5: v2(1230.34,2879.54) 1230.34,2865.07 1237.38,2858.03 1237.38,2830.63 U1_4.J13@1232.3,2825.55
  L8 BOTTOM w7.75: R8_4.1@1014.55,2887.78 1054.17,2887.78 1084.72,2918.33 1156.62,2918.33 1175.57,2899.38 1210.5,2899.38 v2(1230.34,2879.54)
TMP1_3V3: C195.1 C196.1 R164.2 U9.5 | length 275.9
  L8 BOTTOM w10: C196.1@1643.31,3074.22 C195.1@1686.31,3074.21 U9.5@1686.31,3022.83 ; C195.1@1685.85,3074.67 1730.43,3074.67 1738.85,3083.09 1738.85,3145.2 1713.84,3170.21 R164.2@1686.31,3170.21
TMP1_ADD0: R165.2 U9.4 | length 90.5
  L8 BOTTOM w7.75: R165.2@1600.31,3074.23 1637.33,3037.21 1657.15,3037.21 1666.62,3027.74 U9.4@1666.62,3022.83
TMP2_3V3: C199.1 C200.1 R172.2 R173.2 U10.5 | length 164.8
  L8 BOTTOM w12: R172.2@4097.47,3138.59 C199.1@4138.47,3138.59 ; U10.5@4138.47,3096.82 C199.1@4138.47,3138.59 ; R173.2@4220.47,3138.59 C200.1@4179.47,3138.59 C199.1@4138.47,3138.59
TMP2_ADD0: R172.1 U10.4 | length 136
  L8 BOTTOM w7.75: R172.1@4097.47,3185.83 4097.47,3179.4 4070.26,3152.19 4070.26,3118.68 4092.11,3096.82 U10.4@4118.78,3096.82
TMP_ALERT: R166.1 R171.1 U9.3 U10.3 | length 6598.6
  L1 TOP w10.5: R166.1@3870,4570.25 v2(3870,4604.76)
  L6 SIGNAL 3 w6.9: v2(1851.79,3243.79) 1851.79,3356.51 1959.25,3463.97 2149.42,3463.97 2215.05,3529.6 2704.08,3529.6 2961.93,3787.44 3073.61,3787.44 3296.09,4009.92 3296.09,4081.84 3228.63,4149.3 3228.63,4253.11 3219.81,4261.93 3219.81,4332.93 3202.98,4349.76 3202.98,4475.74 3223.09,4495.85 3223.09,4554.55 3300.9,4632.36 3490.56,4632.36 3523.75,4665.54 3722.99,4665.54 3753.7,4634.83 3839.93,4634.83 v2(3870,4604.76) 3899.9,4634.67 4011.69,4634.67 4139.57,4762.54 4411.8,4762.54 4796.75,4377.59 4796.75,3795.11 v2(4260.89,3259.25)
  L8 BOTTOM w7.75: U9.3@1666.62,2964.56 1666.62,2988.77 1669.85,2992 1712.42,2992 1851.79,3131.37 v2(1851.79,3243.79) ; R171.1@3870,4570.25 v2(3870,4604.76) ; U10.3@4118.78,3038.55 4118.78,3043.11 4111.62,3050.28 4081.14,3050.28 4024.49,3106.92 4024.49,3223.92 4091.57,3291 4229.14,3291 v2(4260.89,3259.25)
TMPSNS_ALERT: J5.57 R171.2 | length 184.2
  L8 BOTTOM w7.75: J5.57@3806.57,4365.06 3806.57,4401.09 3811.83,4406.34 3811.83,4456.14 3870,4514.31 R171.2@3870,4523
TMPSNS_SCL: R167.1 R170.1 U9.1 U10.1 | length 7378.8
  L1 TOP w10.5: R170.1@3624,4570.25 v2(3624,4603.07)
  L6 SIGNAL 3 w6.9: v2(1836.72,3078.07) 1836.72,3163.55 1909.35,3236.18 1909.35,3354.77 1981.58,3427 2165.17,3427 2235,3496.84 2780.31,3496.84 2865.28,3411.88 2865.28,2847.05 3348.79,2363.54 3785.84,2363.54 3903.46,2481.16 3903.46,2767.71 3834.43,2836.73 3834.43,2938.96 3819.98,2953.41 3819.98,2969.32 3831.77,2981.11 3850.7,2981.11 3871.14,2960.67 3893.33,2960.67 4025.02,3092.36 v2(4200.55,3092.36) 4200.55,3134.02 4197.18,3137.39 4197.18,3269.03 4216.87,3288.72 4255.16,3288.72 4745.78,3779.34 4745.78,4371.13 4378.51,4738.4 4167.47,4738.4 4009.39,4580.32 3646.75,4580.32 v2(3624,4603.07)
  L8 BOTTOM w7.75: U9.1@1705.99,2964.56 1705.99,2966.6 1714.62,2975.23 1733.87,2975.23 v2(1836.72,3078.07) ; v2(3624,4603.07) R167.1@3624,4640.08 ; U10.1@4158.15,3038.55 4158.15,3045.47 4167.75,3055.07 4167.75,3059.56 v2(4200.55,3092.36)
TMPSNS_SDA: R168.1 R169.1 U9.6 U10.6 | length 6413.7
  L1 TOP w10.5: v2(3562.86,4606.14) 3583,4586 R168.1@3583,4547.25
  L6 SIGNAL 3 w6.9: v2(1829.07,3264) 1829.07,3229.67 1840.54,3218.2 1869.51,3218.2 1892.89,3241.58 1892.89,3367.1 1968.38,3442.59 2155.21,3442.59 2225.27,3512.65 2713.71,3512.65 2955.24,3754.18 3059.55,3754.18 3307.99,4002.62 3307.99,4088.83 3275.04,4121.78 3275.04,4311.71 3217.96,4368.78 3217.96,4468.54 3238.49,4489.07 3238.49,4544.9 3312.34,4618.75 3491.1,4618.75 3503.71,4606.14 v2(3562.86,4606.14) 3604.66,4564.34 4021.42,4564.34 4169.37,4712.3 4348.6,4712.3 4697.81,4363.09 4697.81,3764.14 4241.94,3308.27 4177.71,3308.27 4135.57,3266.13 v2(4135.57,3246.81)
  L8 BOTTOM w7.75: U9.6@1705.99,3022.83 1705.99,3035.16 1716.84,3046.01 1737.84,3046.01 1829.07,3137.24 v2(1829.07,3264) ; v2(3562.86,4606.14) 3583,4586 R169.1@3583,4547.25 ; v2@4132.57,3247.81 4131.57,3246.81 4073.65,3246.81 4038.13,3211.29 4038.13,3123.3 4094.25,3067.18 4148.96,3067.18 4158.15,3076.37 U10.6@4158.15,3096.82
UART_TX_RS_1: R11_1.2 U1_1.N6 | length 260
  L1 TOP w4: 2239.39,3137.04 2279.26,3137.04 2286.94,3129.36 2286.94,3111.68 U1_1.N6@2299.94,3098.68
  L1 TOP w6: v2(2141,3229) 2142.82,3229 2234.78,3137.04 2239.39,3137.04
  L8 BOTTOM w7.75: R11_1.2@2104.31,3229 v2(2141,3229)
UART_TX_RS_2: R11_2.2 U1_2.N6 | length 260.2
  L1 TOP w4: 4545.88,3052.12 4554.96,3043.04 4597.26,3043.04 4604.94,3035.36 4604.94,3017.68 U1_2.N6@4617.94,3004.68
  L1 TOP w4.9: v2(4459,3135) 4463,3135 4545.88,3052.12
  L8 BOTTOM w7.75: R11_2.2@4422.06,3135 v2(4459,3135)
UART_TX_RS_3: R11_3.2 U1_3.N6 | length 374.7
  L1 TOP w4: v2(3481,3232) 3481,3213.65 3557.61,3137.04 3594.26,3137.04 3601.94,3129.36 3601.94,3111.68 U1_3.N6@3614.94,3098.68
  L8 BOTTOM w7.75: v2(3481,3232) 3481,3303 3517.92,3339.92 3517.92,3378.43 R11_3.2@3516,3380.34
UART_TX_RS_4: R11_4.2 U1_4.N6 | length 257.4
  L1 TOP w4: 1059.1,3051.9 1067.96,3043.04 1109.26,3043.04 1116.94,3035.36 1116.94,3017.68 U1_4.N6@1129.94,3004.68
  L1 TOP w6: v2(970,3133) 978,3133 1059.1,3051.9
  L8 BOTTOM w7.75: v2(970,3133) 1003.85,3133 R11_4.2@1003.91,3132.94
XWR_CONN_TP1: J4.22 TP12.1 | length 140.8
  L8 BOTTOM w7.75: J4.22@3117.6,979.24 3117.6,1018.08 3125.61,1026.1 TP12.1@3125.61,1116.7
XWR_CONN_TP2: J4.52 TP15.1 | length 115.8
  L8 BOTTOM w7.75: J4.52@3708.15,979.24 3709,980.09 TP15.1@3709,1094.73
XWR_CONN_TP3: J5.69 TP8.1 | length 106.3
  L8 BOTTOM w7.75: TP8.1@2854.35,4025.61 2854.35,4076.29 2861.69,4083.63 J5.69@2861.69,4128.84
XWR_CONN_TP4: J5.99 TP13.1 | length 122.8
  L8 BOTTOM w7.75: TP13.1@3425.79,4016.95 3452.24,4043.4 J5.99@3452.24,4128.84
pads on no net: FID1.1 FID2.1 FID3.1 FID4.1 FID5.1 FID6.1 J6.ALIGN1 J6.ALIGN2 U1_1.G13 U1_2.G13 U1_3.G13 U1_4.G13 U2_1. U2_2. U2_3. U2_4. U3. U4. U5.2 U5.6 U5.7
copper on no net: | length 4000.2
  L1 TOP w10: 1212.01,-25.99 1333.89,-25.99 1333.89,102.14 1212.01,102.14 1212.01,-25.99
  L2 GND w10: 1212.01,-25.99 1212.01,102.14 1333.89,102.14 1333.89,-25.99 1212.01,-25.99
  L3 SIGNAL 1 w10: 1212.01,-25.99 1212.01,102.14 1333.89,102.14 1333.89,-25.99 1212.01,-25.99
  L4 GND w10: 1212.01,-25.99 1212.01,102.14 1333.89,102.14 1333.89,-25.99 1212.01,-25.99
  L5 SIGNAL 2 w10: 1212.01,-25.99 1212.01,102.14 1333.89,102.14 1333.89,-25.99 1212.01,-25.99
  L6 SIGNAL 3 w10: 1212.01,-25.99 1333.89,-25.99 1333.89,102.14 1212.01,102.14 1212.01,-25.99
  L7 GND w10: 1212.01,-25.99 1212.01,102.14 1333.89,102.14 1333.89,-25.99 1212.01,-25.99
  L8 BOTTOM w10: 1212.01,-25.99 1212.01,102.14 1333.89,102.14 1333.89,-25.99 1212.01,-25.99

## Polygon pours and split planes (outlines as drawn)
12XX_2_1V0_RF1_FILT on L1 TOP "L1_TOP_12XX_2_1V0_RF1_FILT_P29666" (solid, remove dead copper, pour order 29666): 27 vertices, not listed, extent 5498.68,302.32 6142.7,2147.42
GND on L1 TOP "L1_TOP_GND_P29669" (solid, remove dead copper, pour order 29669): 18 vertices, not listed, extent -130.19,1888.68 739.5,5239.33
GND on L1 TOP "L1_TOP_GND_P29668" (solid, remove dead copper, pour order 29668): 5231.8,5238.53 5231.69,4849.43 5283.95,4797.16 5716.26,4797.16 5796.07,4717.35 5796.07,2190.14 5810.92,2175.29 6168.01,2175.29 6168.57,2175.85 6168.57,5231.61 6161.65,5238.53
PMIC2_VIN_B3 on L1 TOP "L1_TOP_PMIC2_VIN_B3_P29651" (solid, remove dead copper, pour order 29651): 17 vertices, not listed, extent 5235.05,983.99 5387.52,1217.43
PMIC2_VIN_B2 on L1 TOP "L1_TOP_PMIC2_VIN_B2_P29652" (solid, remove dead copper, pour order 29652): 17 vertices, not listed, extent 5521,983.99 5673.48,1217.43
PMIC2_VIN_B0 on L1 TOP "L1_TOP_PMIC2_VIN_B0_P29649" (solid, remove dead copper, pour order 29649): 17 vertices, not listed, extent 5521,732.78 5673.48,966.22
PMIC2_VIN_B1 on L1 TOP "L1_TOP_PMIC2_VIN_B1_P29646" (solid, remove dead copper, pour order 29646): 17 vertices, not listed, extent 5235.05,732.78 5387.52,966.22
GND on L1 TOP "L1_TOP_GND_P29635" (solid, remove dead copper, pour order 29635): 5297.25,1118.41 5291.49,1112.65 5288.65,1112.65 5258.14,1082.13 5251.24,1075.23 5229.56,1075.23 5192.22,1112.57 5192.22,1150.63 5196.88,1155.3 5214.33,1155.3 5297.25,1155.3
GND on L1 TOP "L1_TOP_GND_P29632" (solid, remove dead copper, pour order 29632): 5611.28,1118.41 5617.04,1112.65 5619.88,1112.65 5650.39,1082.13 5657.29,1075.23 5678.97,1075.23 5716.3,1112.57 5716.3,1150.63 5711.64,1155.3 5694.19,1155.3 5611.28,1155.3
GND on L1 TOP "L1_TOP_GND_P29628" (solid, remove dead copper, pour order 29628): 5685.04,794.92 5689.22,794.92 5695.63,801.32 5695.63,858.35 5690.3,863.64 5678.97,874.98 5657.29,874.98 5650.39,868.08 5619.88,837.57 5617.04,837.57 5611.28,831.8 5611.28,794.92
GND on L1 TOP "L1_TOP_GND_P29631" (solid, remove dead copper, pour order 29631): 5297.25,831.8 5291.49,837.57 5288.65,837.57 5258.14,868.08 5251.24,874.98 5229.56,874.98 5192.22,837.64 5192.22,799.58 5196.88,794.92 5214.33,794.92 5297.25,794.92
PMIC1_VIN_B1 on L1 TOP "L1_TOP_PMIC1_VIN_B1_P29653" (solid, remove dead copper, pour order 29653): 17 vertices, not listed, extent 364.32,1520.64 516.8,1754.08
PMIC1_VIN_B0 on L1 TOP "L1_TOP_PMIC1_VIN_B0_P29650" (solid, remove dead copper, pour order 29650): 17 vertices, not listed, extent 650.28,1520.64 802.75,1754.08
GND on L1 TOP "L1_TOP_GND_P29634" (solid, remove dead copper, pour order 29634): 426.53,1619.66 420.76,1625.42 417.93,1625.42 387.41,1655.93 380.51,1662.84 358.83,1662.84 321.5,1625.5 321.5,1587.43 326.16,1582.77 343.61,1582.77 426.53,1582.77
GND on L1 TOP "L1_TOP_GND_P29629" (solid, remove dead copper, pour order 29629): 814.32,1582.77 818.5,1582.77 824.9,1589.18 824.9,1646.21 819.58,1651.5 808.24,1662.84 786.56,1662.84 779.66,1655.93 749.15,1625.42 746.31,1625.42 740.55,1619.66 740.55,1582.77
PMIC1_VIN_B2 on L1 TOP "L1_TOP_PMIC1_VIN_B2_P29648" (solid, remove dead copper, pour order 29648): 17 vertices, not listed, extent 650.28,1771.85 802.75,2005.29
PMIC1_3V3 on L1 TOP "L1_TOP_PMIC1_3V3_P29665" (solid, remove dead copper, pour order 29665): 19 vertices, not listed, extent 16.21,912.48 1168.2,1913.4
GND on L1 TOP "L1_TOP_GND_P29633" (solid, remove dead copper, pour order 29633): 740.55,1906.26 746.31,1900.5 749.15,1900.5 779.66,1869.99 786.56,1863.09 808.24,1863.09 845.58,1900.42 845.58,1938.49 840.92,1943.15 823.47,1943.15 740.55,1943.15
GND on L1 TOP "L1_TOP_GND_P29657" (solid, remove dead copper, pour order 29657): 531.43,1772.95 531.43,1505.92 532.07,1505.28 635.01,1505.28 635.01,1772.95
GND on L1 TOP "L1_TOP_GND_P29654" (solid, remove dead copper, pour order 29654): 531.43,1762.96 531.43,2020.01 532.07,2020.65 635.01,2020.65 635.01,1762.96
GND on L1 TOP "L1_TOP_GND_P29658" (solid, remove dead copper, pour order 29658): 4307.89,1313.25 4657.16,1313.25 4685.8,1284.61 4685.8,1111.12 4658.13,1083.45 4307.12,1083.45 4270.23,1120.34 4270.23,1275.59
SYSTEM_3V3 on L1 TOP "L1_TOP_SYSTEM_3V3_P29638" (solid, remove dead copper, pour order 29638): 4331.55,451.55 4327.93,455.18 4327.93,563.8 4323.09,568.63 4292.02,568.63 4283.95,576.69 4283.95,596.33 4291.96,604.34 4375.47,604.34 4381.38,598.43 4381.38,471.46 4361.47,451.55
SYSTEM_3V3 on L1 TOP "L1_TOP_SYSTEM_3V3_P29637" (solid, remove dead copper, pour order 29637): 4638,451.55 4634.38,455.18 4634.38,563.8 4629.54,568.63 4598.47,568.63 4590.4,576.69 4590.4,596.33 4598.41,604.34 4681.92,604.34 4687.83,598.43 4687.83,471.46 4667.92,451.55
SYSTEM_3V3 on L1 TOP "L1_TOP_SYSTEM_3V3_P29640" (solid, remove dead copper, pour order 29640): 3495.38,4764.67 3639.41,4764.67 3659.54,4784.79 3659.54,4814.71 3647.09,4827.15 3493.27,4827.15 3489.56,4823.44 3489.56,4770.34 3495.03,4764.87
SYSTEM_3V3 on L1 TOP "L1_TOP_SYSTEM_3V3_P29639" (solid, remove dead copper, pour order 29639): 3495.38,4997.71 3639.41,4997.71 3659.54,5017.83 3659.54,5047.75 3647.09,5060.2 3493.27,5060.2 3489.56,5056.49 3489.56,5003.38 3495.03,4997.91
SYSTEM_3V3 on L1 TOP "L1_TOP_SYSTEM_3V3_P29645" (solid, remove dead copper, pour order 29645): 2469.56,5061.01 2469.56,5142.27 2440.5,5171.33 2341.73,5171.33 2332.39,5161.99 2332.39,5085.55 2358.97,5058.96 2467.78,5058.96 2469.27,5060.45
SYSTEM_5V0 on L1 TOP "L1_TOP_SYSTEM_5V0_P29664" (solid, remove dead copper, pour order 29664): 2493.84,527.93 2581.97,527.93 2745.05,364.84 3931.77,364.84 3982.95,313.66 3982.95,96.49 3958.62,72.16 2507.28,72.16 2482.39,97.05 2482.39,516.58 2493.72,527.9
GND on L1 TOP "L1_TOP_GND_P29655" (solid, remove dead copper, pour order 29655): 5402.15,975.11 5402.15,1232.15 5402.79,1232.79 5505.73,1232.79 5505.73,975.11
SYSTEM_5V0 on L1 TOP "L1_TOP_SYSTEM_5V0_P29663" (solid, remove dead copper, pour order 29663): 5324.09,1251.7 5584.64,1251.7 5709.88,1376.94 5709.88,1685.56 5650.94,1744.51 5259.54,1744.51 5212.77,1697.74 5212.77,1363.02
SYSTEM_5V0 on L1 TOP "L1_TOP_SYSTEM_5V0_P29661" (solid, remove dead copper, pour order 29661): 5324.09,698.51 5584.64,698.51 5709.88,573.27 5709.88,264.65 5650.94,205.7 5259.54,205.7 5212.77,252.47 5212.77,587.19
GND on L1 TOP "L1_TOP_GND_P29656" (solid, remove dead copper, pour order 29656): 5402.15,985.09 5402.15,718.06 5402.79,717.42 5505.73,717.42 5505.73,985.09
SYSTEM_5V0 on L1 TOP "L1_TOP_SYSTEM_5V0_P29660" (solid, remove dead copper, pour order 29660): 453.36,1486.37 713.92,1486.37 839.16,1361.13 839.16,1052.5 780.21,993.56 388.81,993.56 342.04,1040.33 342.04,1375.04
SYSTEM_5V0 on L1 TOP "L1_TOP_SYSTEM_5V0_P29662" (solid, remove dead copper, pour order 29662): 453.36,2039.56 713.92,2039.56 839.16,2164.79 839.16,2473.42 780.21,2532.36 388.81,2532.36 342.04,2485.6 342.04,2150.88
GND on L1 TOP "L1_TOP_GND_P29636" (solid, remove dead copper, pour order 29636): 426.53,1906.26 420.76,1900.5 417.93,1900.5 387.41,1869.99 380.51,1863.09 358.83,1863.09 321.5,1900.42 321.5,1938.49 326.16,1943.15 343.61,1943.15 426.53,1943.15
PMIC1_VIN_B3 on L1 TOP "L1_TOP_PMIC1_VIN_B3_P29647" (solid, remove dead copper, pour order 29647): 17 vertices, not listed, extent 364.32,1771.85 516.8,2005.29
SYSTEM_5V0 on L1 TOP "L1_TOP_SYSTEM_5V0_P29659" (solid, remove dead copper, pour order 29659): 541.5,559.71 541.5,810.02 572.8,841.28 1056.63,841.28 1100.04,797.87 1100.04,543.34 1059.51,502.81 598,502.81
SYSTEM_1V8 on L1 TOP "L1_TOP_SYSTEM_1V8_P29643" (solid, remove dead copper, pour order 29643): 3239.31,4840.49 3280.27,4840.68 3297.05,4823.9 3372.17,4823.9 3378.31,4817.76 3378.31,4753.78 3360.42,4735.89 3252.14,4735.89 3236.26,4751.77 3236.26,4837.44
12XX_4_1V2_FILT on L1 TOP "L1_TOP_12XX_4_1V2_FILT_P29625" (solid, remove dead copper, pour order 29625): 978.08,2667.46 1045.42,2667.46 1045.42,2701.47 1019.13,2701.47 1002.59,2718.02 987.19,2718.02 968.35,2699.18 968.35,2672.52 973.4,2667.46
12XX_1_1V0_RF2_FILT on L1 TOP "L1_TOP_12XX_1_1V0_RF2_FILT_P29626" (solid, remove dead copper, pour order 29626): 2780.9,3259.52 2780.72,3232 2795.92,3216.8 2795.92,3194.71 2809.16,3181.48 2831.86,3181.48 2839.55,3189.17 2839.55,3252.46 2832.49,3259.52
12XX_2_1V0_RF2_FILT on L1 TOP "L1_TOP_12XX_2_1V0_RF2_FILT_P29627" (solid, remove dead copper, pour order 29627): 5110.63,3106.67 5126.99,3123.04 5126.99,3180.3 5133.93,3187.24 5172.42,3187.24 5177.47,3182.19 5177.47,3099.33 5168.43,3090.29 5116.66,3090.29 5110.29,3096.65 5110.29,3106.32
GND on L1 TOP "L1_TOP_GND_P29630" (solid, remove dead copper, pour order 29630): 2620.27,2620.24 2699.18,2620.24 2708.95,2630 2708.95,2673.93 2698.64,2684.24 2622.44,2684.24 2615.93,2677.73 2615.93,2624.55 2620.1,2620.38
GND on L1 TOP "L1_TOP_GND_P29641" (solid, remove dead copper, pour order 29641): 3765.34,2626.13 3895.98,2626.13 3902.5,2619.61 3902.5,2553.55 3882.95,2534 3797.04,2534 3758.83,2572.21 3758.83,2619.64 3765.26,2626.08
GND on L1 TOP "L1_TOP_GND_P29642" (solid, remove dead copper, pour order 29642): 2456.44,2602.38 2582.21,2602.38 2592.43,2592.16 2592.43,2521.18 2573.41,2502.16 2503.29,2502.16 2456.48,2548.96 2456.48,2602.13
12XX_3_1V0_RF2_FILT on L1 TOP "L1_TOP_12XX_3_1V0_RF2_FILT_P29644" (solid, remove dead copper, pour order 29644): 4060.58,3291.1 4060.25,3375.78 4020.02,3416.01 4020.02,3467.38 4035.05,3482.4 4079.64,3482.4 4116.47,3445.57 4116.47,3292.27 4114.26,3290.06 4061.61,3290.06
GND on L1 TOP "L1_TOP_GND_P29667" (solid, remove dead copper, pour order 29667): 2270.5,5238.6 2270.5,4661.99 4264.81,4661.99 4264.91,5225.92 4252.58,5238.25
GND on L1 TOP "L1_TOP_GND_P29670" (solid, remove dead copper, pour order 29670): 18 vertices, not listed, extent -131,-131 6167.79,831.86
GND on L1 TOP "L1_TOP_GND_P29671" (solid, remove dead copper, pour order 29671): 31 vertices, not listed, extent 501.19,1828.74 5503.18,4018.89
GND on L8 BOTTOM "L8_BOTTOM_GND_P29798" (solid, remove dead copper, pour order 29798): -131,-131 6168.21,-131 6168.21,5239.07 -131,5239.07
12XX_2_1V8_FILT on L8 BOTTOM "L8_BOTTOM_12XX_2_1V8_FILT_P29795" (solid, remove dead copper, pour order 29795): 24 vertices, not listed, extent 4635.81,1462.49 5451.53,3426.65
12XX_4_1V2_FILT on L8 BOTTOM "L8_BOTTOM_12XX_4_1V2_FILT_P29785" (solid, remove dead copper, pour order 29785): 946.33,2849.94 946.33,2640.24 1025.35,2561.22 1267.72,2561.22 1352.06,2645.56 1352.06,2844.62 1328.51,2868.17 1214.57,2868.17 1164.42,2918.32 1014.74,2918.32 946.86,2850.43
12XX_2_1V0_RF2_FILT on L8 BOTTOM "L8_BOTTOM_12XX_2_1V0_RF2_FILT_P29782" (solid, remove dead copper, pour order 29782): 4829.9,3085.09 4829.91,3051.54 4843.19,3038.26 4987.81,3038.26 5172.62,2853.46 5259.54,2853.46 5280.15,2874.07 5280.15,2992.52 5148.12,3124.55 4929.75,3124.55 4905.21,3100.02 4844.82,3100.02
PMIC1_SW_B2 on L8 BOTTOM "L8_BOTTOM_PMIC1_SW_B2_P29712" (solid, remove dead copper, pour order 29712): 602.33,1904.39 626.6,1928.65 626.6,1991.13 635.88,2000.41 720.21,2000.41 725.65,1994.97 725.65,1925.86 722.09,1922.3 640.83,1922.3 602.33,1883.81
PMIC1_SW_B0 on L8 BOTTOM "L8_BOTTOM_PMIC1_SW_B0_P29710" (solid, remove dead copper, pour order 29710): 602.33,1621.53 626.6,1597.27 626.6,1534.8 635.88,1525.51 720.21,1525.51 725.65,1530.95 725.65,1600.06 722.09,1603.62 640.83,1603.62 602.33,1642.11
PMIC2_SW_B2 on L8 BOTTOM "L8_BOTTOM_PMIC2_SW_B2_P29706" (solid, remove dead copper, pour order 29706): 5473.06,1116.54 5497.32,1140.8 5497.32,1203.27 5506.6,1212.56 5590.94,1212.56 5596.38,1207.12 5596.38,1138 5592.82,1134.45 5511.55,1134.45 5473.06,1095.96
PMIC2_SW_B0 on L8 BOTTOM "L8_BOTTOM_PMIC2_SW_B0_P29705" (solid, remove dead copper, pour order 29705): 5473.06,833.68 5497.32,809.41 5497.32,746.94 5506.6,737.66 5590.94,737.66 5596.38,743.09 5596.38,812.21 5592.82,815.77 5511.55,815.77 5473.06,854.26
12XX_3_1V0_RF1_FILT on L8 BOTTOM "L8_BOTTOM_12XX_3_1V0_RF1_FILT_P29797" (solid, remove dead copper, pour order 29797): 33 vertices, not listed, extent 3666.48,1292.25 6169.01,4069.04
GND on L8 BOTTOM "L8_BOTTOM_GND_P29725" (solid, remove dead copper, pour order 29725): 3685.47,3174.35 3685.47,3218.83 3674.83,3229.48 3674.83,3290.31 3664.18,3300.95 3637.19,3300.95 3624.74,3288.5 3555.4,3288.5 3540.11,3273.2 3540.11,3235.31 3602.19,3173.23 3684.09,3173.23 3685.18,3174.32
SYSTEM_5V0 on L8 BOTTOM "L8_BOTTOM_SYSTEM_5V0_P29796" (solid, remove dead copper, pour order 29796): 35 vertices, not listed, extent 2341.19,4319.37 4314.2,5222.32
12XX_3_1V0_RF2_FILT on L8 BOTTOM "L8_BOTTOM_12XX_3_1V0_RF2_FILT_P29794" (solid, remove dead copper, pour order 29794): 27 vertices, not listed, extent 3834.53,1471.72 5878.58,3778.59
12XX_3_1V2_FILT on L8 BOTTOM "L8_BOTTOM_12XX_3_1V2_FILT_P29793" (solid, remove dead copper, pour order 29793): 17 vertices, not listed, extent 3913.74,-34.67 5218.82,1138.73
12XX_4_1V0_RF2_FILT on L8 BOTTOM "L8_BOTTOM_12XX_4_1V0_RF2_FILT_P29789" (solid, remove dead copper, pour order 29789): 33 vertices, not listed, extent 831.95,2091.89 1874.36,3214.6
12XX_1_1V0_RF2_FILT on L8 BOTTOM "L8_BOTTOM_12XX_1_1V0_RF2_FILT_P29788" (solid, remove dead copper, pour order 29788): 981.95,1099.93 981.95,1069.48 998.6,1052.83 1531.52,1052.83 1576.14,1008.21 1576.14,679.16 1544.46,647.48 1097.4,647.48 834.88,910 834.88,1058.8 835,1272.41 841.07,1278.48 969.61,1278.48 981.95,1266.14
GND on L8 BOTTOM "L8_BOTTOM_GND_P29720" (solid, remove dead copper, pour order 29720): 17 vertices, not listed, extent 324.94,1483.32 435.27,1662.2
GND on L8 BOTTOM "L8_BOTTOM_GND_P29721" (solid, remove dead copper, pour order 29721): 17 vertices, not listed, extent 731.81,1483.32 842.14,1662.2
